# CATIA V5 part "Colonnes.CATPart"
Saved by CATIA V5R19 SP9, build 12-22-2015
Part number: Colonnes
Bounding box of the stored display mesh (mm): x 0 to 680, y -9 to 184, z -9 to 418
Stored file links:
  Z:\fausse table rondelle-20220905T211342Z-001\fausse table rondelle\Colonnes.CATPart
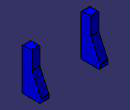
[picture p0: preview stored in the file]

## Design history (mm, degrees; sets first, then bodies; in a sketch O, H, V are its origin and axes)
AxisSystem1: origin (0, 0, 0), X (1, 0, 0), Y (0, 1, 0), Z (0, 0, 1)
Body1 (main body)
  Sketch1 on YZ plane of AxisSystem1, origin (0, 0, 0), H (0, 1, 0), V (0, 0, 1)
    point P1 (-9, -9)
    line L1 (-9, -9) -> (-9, 418)
    line L2 (-9, 418) -> (91, 418)
    line L3 (91, 418) -> (91, 243)
    line L4 (91, 243) -> (184, 39)
    line L5 (184, 39) -> (184, -9)
    line L6 (184, -9) -> (-9, -9)
    reference projected line E1 through (0, 0) direction (1, 0) from edge [YZ plane of AxisSystem1 | XY plane of AxisSystem1]
    distance P1 V = 9
    distance E1 L6 = 9
    distance L1 L3 = 100
    length L5 = 48
    distance L5 L1 = 193
    distance L2 L6 = 427
    length L3 = 175
    vertical: L1 V, L3 V, L5 V
    horizontal: L2 H, L6 H
  Pad1: profile Sketch1, direction (1, 0, 0), length 680
  Fillet1: radius 10, on edge [face of Pad1 from Sketch1.L2 | face of Pad1 from Sketch1.L3]; edge [face of Pad1 from Sketch1.L1 | face of Pad1 from Sketch1.L2]; edge [face of Pad1 from Sketch1.L3 | face of Pad1 from Sketch1.L4]; edge [face of Pad1 from Sketch1.L4 | face of Pad1 from Sketch1.L5]; edge [face of Pad1 from Sketch1.L5 | face of Pad1 from Sketch1.L6]; edge [face of Pad1 from Sketch1.L6 | face of Pad1 from Sketch1.L1]
  Sketch2 on YZ plane of AxisSystem1, origin (0, 0, 0), H (0, 1, 0), V (0, 0, 1)
    line L1 (-186.9263, 516.5533) -> (474.852, 516.5533)
    line L2 (474.852, 516.5533) -> (474.852, -129.6289)
    line L3 (474.852, -129.6289) -> (-186.9263, -129.6289)
    line L4 (-186.9263, -129.6289) -> (-186.9263, 516.5533)
    horizontal: L1 H, L3 H
    vertical: L2 V, L4 V
  Pocket1: profile Sketch2, direction (1, 0, 0), up to end face of Pad1, offset -80, opposite side up to start face of Pad1, offset -80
